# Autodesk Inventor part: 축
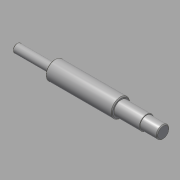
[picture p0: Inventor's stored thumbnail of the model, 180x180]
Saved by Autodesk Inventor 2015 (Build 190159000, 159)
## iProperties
Created: 2016-05
Part Number: 축
Document SubType Name: Modeling
Designer: mduedu
Density: 7.86 g/cm^3
Material: 강철, 연강
Appearance: 강철
Author: mduedu
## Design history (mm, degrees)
sketch "스케치1"
  geometry: L1 (-42, 11)-(-42, 5); L2 (37, 11)-(37, 8.5); L3 (-87, 0)-(87, 0); L4 (-42, 11)-(37, 11); L5 (37, 11)-(37, 8.5); L6 (-42, 11)-(-42, 5); L7 (-42, 5)-(-87, 5); L8 (-87, 5)-(-87, 0); L9 (37, 8.5)-(67, 8.5); L10 (87, 7.5)-(87, 0); L11 (67, 8.5)-(67, 7.5); L12 (67, 7.5)-(87, 7.5); 1 further point
  constraints: 24 end point, 9 perpendicular, 2 midpoint, 1 horizontal
  dimensions: "d0" = 22 diameter of L4 L3; "d1" = 10 diameter of L7 L3; "d2" = 45 distance between parallel lines of L8 L1; "d3" = 50 distance between parallel lines of L10 L2; "d4" = 15 diameter of L12 L3; "d5" = 20 distance between parallel lines of L10 L11; "d29" = 79 distance of L1.start L2.start; "d37" = 17 diameter of L9 L3
revolve "회전1" stored, may be unused: angle "d6" = 90 deg
chamfer "모따기2" distance "d32" = 1; stored, may be unused: second distance "d33" = 2, angle "d34" = 45 deg
node "작업 평면4"
sketch "스케치4"
  geometry: L1 (-5, 2.5)-(5, 2.5); L2 (5, -2.5)-(-5, -2.5); L3 (-10, -6.5)-(-10, 6.5) reference; A1 r 2.5 centre (5, 0) between (5, -2.5) and (5, 2.5); A2 r 2.5 centre (-5, 0) between (-5, 2.5) and (-5, -2.5); 1 further point
  constraints: 4 end point, 4 point on circle, 4 tangent, 2 centre point, 1 horizontal, 1 horizontal alignment, 1 parallel
  dimensions: "d20" = 5 distance between parallel lines of L2 L1; "d21" = 15 dimension on A1 A2; "d35" = 2.5 distance edge to line of A2 L3
extrude "돌출3" cut sketch "스케치4" distance "d23" = 3; taper "d24" = 0 deg
node "작업 평면5"
sketch "스케치5"
  geometry: L1 (22.5, 1.5)-(10, 1.5); L2 (10, -1.5)-(22.5, -1.5); L3 (22.5, 4)-(22.5, -4) reference; A1 r 1.5 centre (10, 0) between (10, 1.5) and (10, -1.5); 3 further points
  constraints: 4 end point, 2 horizontal alignment, 2 point on circle, 2 point on line, 2 tangent, 1 centre point, 1 coincident, 1 horizontal, 1 midpoint
  dimensions: "d25" = 3 distance between parallel lines of L2 L1; "d36" = 14 dimension on A1 L3
extrude "돌출4" cut sketch "스케치5" distance "d27" = 1.8; taper "d28" = 0 deg
node "솔리드1"
